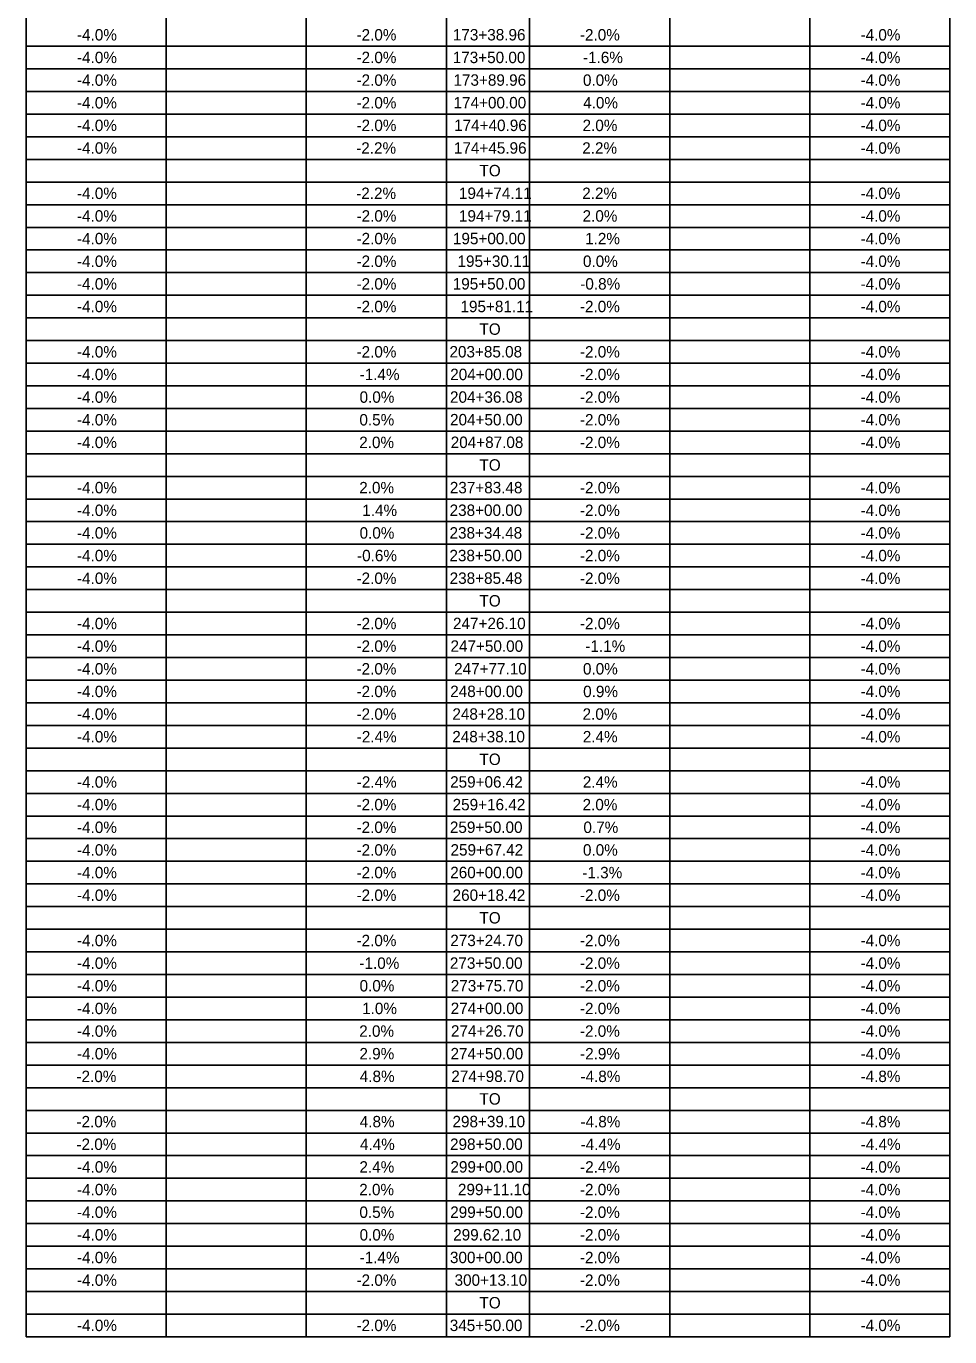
# Model space of a CAD drawing. Extents: x -15319374 to 1762012, y 465773 to 3693661.
# Drawn here: x -15318877.5 to -15318635, y 3691285.9 to 3691629.9 of the extents above; entities that cross this region are included whole.
import ezdxf

# ---------------------------------------------------------------- set-up
doc = ezdxf.new("R2010")
doc.units = 0
doc.layers.add('BORDER', color=7, linetype='Continuous')
doc.layers.add('DIMENSIONS', color=7, linetype='Continuous')

msp = doc.modelspace()

# ---------------------------------------------------------------- linework, layer by layer
at = {"layer": 'BORDER'}
for p, q in [((-15318877.49, 3691969.22), (-15318877.49, 3691464.16)), ((-15318840.73, 3691969.22), (-15318840.73, 3691285.88)), ((-15318803.96, 3691969.22), (-15318803.96, 3691285.88)), ((-15318767.19, 3691969.22), (-15318767.19, 3691285.88)), ((-15318745.32, 3691969.22), (-15318745.32, 3691285.88)), ((-15318708.55, 3691969.22), (-15318708.55, 3691285.88)), ((-15318671.78, 3691969.22), (-15318671.78, 3691285.88)), ((-15318635.01, 3691969.22), (-15318635.01, 3691464.16)), ((-15318877.49, 3691963.35), (-15318877.49, 3691285.88)), ((-15318877.49, 3691624.61), (-15318635.01, 3691624.61)), ((-15318877.49, 3691618.67), (-15318635.01, 3691618.67)), ((-15318877.49, 3691612.73), (-15318635.01, 3691612.73)), ((-15318877.49, 3691606.78), (-15318635.01, 3691606.78)), ((-15318877.49, 3691600.84), (-15318635.01, 3691600.84)), ((-15318877.49, 3691594.9), (-15318635.01, 3691594.9)), ((-15318877.49, 3691588.96), (-15318635.01, 3691588.96)), ((-15318877.49, 3691583.01), (-15318635.01, 3691583.01)), ((-15318877.49, 3691577.07), (-15318635.01, 3691577.07)), ((-15318877.49, 3691571.13), (-15318635.01, 3691571.13)), ((-15318877.49, 3691565.19), (-15318635.01, 3691565.19)), ((-15318877.49, 3691559.24), (-15318635.01, 3691559.24)), ((-15318877.49, 3691553.3), (-15318635.01, 3691553.3)), ((-15318877.49, 3691547.36), (-15318635.01, 3691547.36)), ((-15318877.49, 3691541.41), (-15318635.01, 3691541.41)), ((-15318877.49, 3691535.47), (-15318635.01, 3691535.47)), ((-15318877.49, 3691529.53), (-15318635.01, 3691529.53)), ((-15318877.49, 3691523.59), (-15318635.01, 3691523.59)), ((-15318877.49, 3691517.64), (-15318635.01, 3691517.64)), ((-15318877.49, 3691511.7), (-15318635.01, 3691511.7)), ((-15318877.49, 3691505.76), (-15318635.01, 3691505.76)), ((-15318877.49, 3691499.82), (-15318635.01, 3691499.82)), ((-15318877.49, 3691493.87), (-15318635.01, 3691493.87)), ((-15318877.49, 3691487.93), (-15318635.01, 3691487.93)), ((-15318877.49, 3691481.99), (-15318635.01, 3691481.99)), ((-15318877.49, 3691476.04), (-15318635.01, 3691476.04)), ((-15318877.49, 3691470.1), (-15318635.01, 3691470.1)), ((-15318877.49, 3691464.16), (-15318635.01, 3691464.16)), ((-15318877.49, 3691458.22), (-15318635.01, 3691458.22)), ((-15318877.49, 3691452.27), (-15318635.01, 3691452.27)), ((-15318877.49, 3691446.33), (-15318635.01, 3691446.33)), ((-15318877.49, 3691440.39), (-15318635.01, 3691440.39)), ((-15318877.49, 3691434.45), (-15318635.01, 3691434.45)), ((-15318877.49, 3691428.5), (-15318635.01, 3691428.5)), ((-15318877.49, 3691422.56), (-15318635.01, 3691422.56)), ((-15318877.49, 3691416.62), (-15318635.01, 3691416.62)), ((-15318877.49, 3691410.67), (-15318635.01, 3691410.67)), ((-15318877.49, 3691404.73), (-15318635.01, 3691404.73)), ((-15318877.49, 3691398.79), (-15318635.01, 3691398.79)), ((-15318877.49, 3691392.85), (-15318635.01, 3691392.85)), ((-15318877.49, 3691386.9), (-15318635.01, 3691386.9)), ((-15318877.49, 3691380.96), (-15318635.01, 3691380.96)), ((-15318877.49, 3691375.02), (-15318635.01, 3691375.02)), ((-15318877.49, 3691369.08), (-15318635.01, 3691369.08)), ((-15318877.49, 3691363.13), (-15318635.01, 3691363.13)), ((-15318877.49, 3691357.19), (-15318635.01, 3691357.19)), ((-15318877.49, 3691351.25), (-15318635.01, 3691351.25)), ((-15318877.49, 3691345.31), (-15318635.01, 3691345.31)), ((-15318877.49, 3691339.36), (-15318635.01, 3691339.36)), ((-15318877.49, 3691333.42), (-15318635.01, 3691333.42)), ((-15318877.49, 3691327.48), (-15318635.01, 3691327.48)), ((-15318877.49, 3691321.53), (-15318635.01, 3691321.53)), ((-15318877.49, 3691315.59), (-15318635.01, 3691315.59)), ((-15318877.49, 3691309.65), (-15318635.01, 3691309.65)), ((-15318877.49, 3691303.71), (-15318635.01, 3691303.71)), ((-15318877.49, 3691297.76), (-15318635.01, 3691297.76)), ((-15318877.49, 3691291.82), (-15318635.01, 3691291.82)), ((-15318877.49, 3691285.88), (-15318635.01, 3691285.88))]:
    msp.add_line(p, q, dxfattribs=at)
for points in [[(-15318877.49, 3691969.22), (-15318635.01, 3691969.22), (-15318635.01, 3691624.61), (-15318877.49, 3691624.61)], [(-15318877.49, 3691624.61), (-15318635.01, 3691624.61), (-15318635.01, 3691285.88), (-15318877.49, 3691285.88)]]:
    msp.add_lwpolyline(points, close=True, dxfattribs=at)

# ---------------------------------------------------------------- texts
at = {"layer": 'DIMENSIONS'}
for s, p in [('-4.0%', (-15318864.16, 3691626.1)), ('-2.0%', (-15318790.77, 3691626.1)), ('173+38.96', (-15318765.48, 3691626.12)), ('-2.0%', (-15318732.12, 3691626.1)), ('-4.0%', (-15318658.45, 3691626.1)), ('-4.0%', (-15318864.16, 3691620.16)), ('-2.0%', (-15318790.77, 3691620.16)), ('173+50.00', (-15318765.51, 3691620.17)), ('-1.6%', (-15318731.32, 3691620.16)), ('-4.0%', (-15318658.45, 3691620.16)), ('-4.0%', (-15318864.16, 3691614.21)), ('-2.0%', (-15318790.77, 3691614.21)), ('173+89.96', (-15318765.32, 3691614.23)), ('0.0%', (-15318731.32, 3691614.21)), ('-4.0%', (-15318658.45, 3691614.21)), ('-4.0%', (-15318864.16, 3691608.27)), ('-2.0%', (-15318790.77, 3691608.27)), ('174+00.00', (-15318765.3, 3691608.29)), ('4.0%', (-15318731.27, 3691608.27)), ('-4.0%', (-15318658.45, 3691608.27)), ('-4.0%', (-15318864.16, 3691602.33)), ('-2.0%', (-15318790.77, 3691602.33)), ('174+40.96', (-15318765.15, 3691602.34)), ('2.0%', (-15318731.42, 3691602.33)), ('-4.0%', (-15318658.45, 3691602.33)), ('-4.0%', (-15318864.16, 3691596.39)), ('-2.2%', (-15318790.86, 3691596.39)), ('174+45.96', (-15318765.2, 3691596.4)), ('2.2%', (-15318731.51, 3691596.39)), ('-4.0%', (-15318658.45, 3691596.39)), ('TO', (-15318758.49, 3691590.46)), ('-4.0%', (-15318864.16, 3691584.5)), ('-2.2%', (-15318790.86, 3691584.5)), ('194+74.11', (-15318763.88, 3691584.52)), ('2.2%', (-15318731.51, 3691584.5)), ('-4.0%', (-15318658.45, 3691584.5)), ('-4.0%', (-15318864.16, 3691578.56)), ('-2.0%', (-15318790.77, 3691578.56)), ('194+79.11', (-15318763.88, 3691578.57)), ('2.0%', (-15318731.42, 3691578.56)), ('-4.0%', (-15318658.45, 3691578.56)), ('-4.0%', (-15318864.16, 3691572.62)), ('-2.0%', (-15318790.77, 3691572.62)), ('195+00.00', (-15318765.46, 3691572.63)), ('1.2%', (-15318730.76, 3691572.62)), ('-4.0%', (-15318658.45, 3691572.62)), ('-4.0%', (-15318864.16, 3691566.67)), ('-2.0%', (-15318790.77, 3691566.67)), ('195+30.11', (-15318764.26, 3691566.69)), ('0.0%', (-15318731.32, 3691566.67)), ('-4.0%', (-15318658.45, 3691566.67)), ('-4.0%', (-15318864.16, 3691560.73)), ('-2.0%', (-15318790.77, 3691560.73)), ('195+50.00', (-15318765.51, 3691560.75)), ('-0.8%', (-15318732.03, 3691560.73)), ('-4.0%', (-15318658.45, 3691560.73)), ('-4.0%', (-15318864.16, 3691554.79)), ('-2.0%', (-15318790.77, 3691554.79)), ('195+81.11', (-15318763.48, 3691554.8)), ('-2.0%', (-15318732.12, 3691554.79)), ('-4.0%', (-15318658.45, 3691554.79)), ('TO', (-15318758.49, 3691548.86)), ('-4.0%', (-15318864.16, 3691542.9)), ('-2.0%', (-15318790.77, 3691542.9)), ('203+85.08', (-15318766.37, 3691542.92)), ('-2.0%', (-15318732.12, 3691542.9)), ('-4.0%', (-15318658.45, 3691542.9)), ('-4.0%', (-15318864.16, 3691536.96)), ('-1.4%', (-15318789.96, 3691536.96)), ('204+00.00', (-15318766.17, 3691536.97)), ('-2.0%', (-15318732.12, 3691536.96)), ('-4.0%', (-15318658.45, 3691536.96)), ('-4.0%', (-15318864.16, 3691531.02)), ('0.0%', (-15318789.97, 3691531.02)), ('204+36.08', (-15318766.23, 3691531.03)), ('-2.0%', (-15318732.12, 3691531.02)), ('-4.0%', (-15318658.45, 3691531.02)), ('-4.0%', (-15318864.16, 3691525.07)), ('0.5%', (-15318790.01, 3691525.07)), ('204+50.00', (-15318766.22, 3691525.09)), ('-2.0%', (-15318732.12, 3691525.07)), ('-4.0%', (-15318658.45, 3691525.07)), ('-4.0%', (-15318864.16, 3691519.13)), ('2.0%', (-15318790.06, 3691519.13)), ('204+87.08', (-15318766.04, 3691519.15)), ('-2.0%', (-15318732.12, 3691519.13)), ('-4.0%', (-15318658.45, 3691519.13)), ('TO', (-15318758.49, 3691513.2)), ('-4.0%', (-15318864.16, 3691507.25)), ('2.0%', (-15318790.06, 3691507.25)), ('237+83.48', (-15318766.28, 3691507.26)), ('-2.0%', (-15318732.12, 3691507.25)), ('-4.0%', (-15318658.45, 3691507.25)), ('-4.0%', (-15318864.16, 3691501.3)), ('1.4%', (-15318789.26, 3691501.3)), ('238+00.00', (-15318766.33, 3691501.32)), ('-2.0%', (-15318732.12, 3691501.3)), ('-4.0%', (-15318658.45, 3691501.3)), ('-4.0%', (-15318864.16, 3691495.36)), ('0.0%', (-15318789.97, 3691495.36)), ('238+34.48', (-15318766.35, 3691495.38)), ('-2.0%', (-15318732.12, 3691495.36)), ('-4.0%', (-15318658.45, 3691495.36)), ('-4.0%', (-15318864.16, 3691489.42)), ('-0.6%', (-15318790.63, 3691489.42)), ('238+50.00', (-15318766.38, 3691489.43)), ('-2.0%', (-15318732.12, 3691489.42)), ('-4.0%', (-15318658.45, 3691489.42)), ('-4.0%', (-15318864.16, 3691483.47)), ('-2.0%', (-15318790.77, 3691483.47)), ('238+85.48', (-15318766.32, 3691483.49)), ('-2.0%', (-15318732.12, 3691483.47)), ('-4.0%', (-15318658.45, 3691483.47)), ('TO', (-15318758.49, 3691477.55)), ('-4.0%', (-15318864.16, 3691471.59)), ('-2.0%', (-15318790.77, 3691471.59)), ('247+26.10', (-15318765.44, 3691471.61)), ('-2.0%', (-15318732.12, 3691471.59)), ('-4.0%', (-15318658.45, 3691471.59)), ('-4.0%', (-15318864.16, 3691465.65)), ('-2.0%', (-15318790.77, 3691465.65)), ('247+50.00', (-15318766.1, 3691465.66)), ('-1.1%', (-15318730.71, 3691465.65)), ('-4.0%', (-15318658.45, 3691465.65)), ('-4.0%', (-15318864.16, 3691459.7)), ('-2.0%', (-15318790.77, 3691459.7)), ('247+77.10', (-15318765.15, 3691459.72)), ('0.0%', (-15318731.32, 3691459.7)), ('-4.0%', (-15318658.45, 3691459.7)), ('-4.0%', (-15318864.16, 3691453.76)), ('-2.0%', (-15318790.77, 3691453.76)), ('248+00.00', (-15318766.17, 3691453.78)), ('0.9%', (-15318731.27, 3691453.76)), ('-4.0%', (-15318658.45, 3691453.76)), ('-4.0%', (-15318864.16, 3691447.82)), ('-2.0%', (-15318790.77, 3691447.82)), ('248+28.10', (-15318765.6, 3691447.83)), ('2.0%', (-15318731.42, 3691447.82)), ('-4.0%', (-15318658.45, 3691447.82)), ('-4.0%', (-15318864.16, 3691441.88)), ('-2.4%', (-15318790.72, 3691441.88)), ('248+38.10', (-15318765.63, 3691441.89)), ('2.4%', (-15318731.37, 3691441.88)), ('-4.0%', (-15318658.45, 3691441.88)), ('TO', (-15318758.49, 3691435.95)), ('-4.0%', (-15318864.16, 3691429.99)), ('-2.4%', (-15318790.72, 3691429.99)), ('259+06.42', (-15318766.2, 3691430.01)), ('2.4%', (-15318731.37, 3691429.99)), ('-4.0%', (-15318658.45, 3691429.99)), ('-4.0%', (-15318864.16, 3691424.05)), ('-2.0%', (-15318790.77, 3691424.05)), ('259+16.42', (-15318765.54, 3691424.06)), ('2.0%', (-15318731.42, 3691424.05)), ('-4.0%', (-15318658.45, 3691424.05)), ('-4.0%', (-15318864.16, 3691418.1)), ('-2.0%', (-15318790.77, 3691418.1)), ('259+50.00', (-15318766.26, 3691418.12)), ('0.7%', (-15318731.2, 3691418.1)), ('-4.0%', (-15318658.45, 3691418.1)), ('-4.0%', (-15318864.16, 3691412.16)), ('-2.0%', (-15318790.77, 3691412.16)), ('259+67.42', (-15318766.09, 3691412.18)), ('0.0%', (-15318731.32, 3691412.16)), ('-4.0%', (-15318658.45, 3691412.16)), ('-4.0%', (-15318864.16, 3691406.22)), ('-2.0%', (-15318790.77, 3691406.22)), ('260+00.00', (-15318766.17, 3691406.24)), ('-1.3%', (-15318731.49, 3691406.22)), ('-4.0%', (-15318658.45, 3691406.22)), ('-4.0%', (-15318864.16, 3691400.28)), ('-2.0%', (-15318790.77, 3691400.28)), ('260+18.42', (-15318765.54, 3691400.29)), ('-2.0%', (-15318732.12, 3691400.28)), ('-4.0%', (-15318658.45, 3691400.28)), ('TO', (-15318758.49, 3691394.35)), ('-4.0%', (-15318864.16, 3691388.39)), ('-2.0%', (-15318790.77, 3691388.39)), ('273+24.70', (-15318766.15, 3691388.41)), ('-2.0%', (-15318732.12, 3691388.39)), ('-4.0%', (-15318658.45, 3691388.39)), ('-4.0%', (-15318864.16, 3691382.45)), ('-1.0%', (-15318790.01, 3691382.45)), ('273+50.00', (-15318766.26, 3691382.46)), ('-2.0%', (-15318732.12, 3691382.45)), ('-4.0%', (-15318658.45, 3691382.45)), ('-4.0%', (-15318864.16, 3691376.51)), ('0.0%', (-15318789.97, 3691376.51)), ('273+75.70', (-15318766.03, 3691376.52)), ('-2.0%', (-15318732.12, 3691376.51)), ('-4.0%', (-15318658.45, 3691376.51)), ('-4.0%', (-15318864.16, 3691370.56)), ('1.0%', (-15318789.3, 3691370.56)), ('274+00.00', (-15318766.05, 3691370.58)), ('-2.0%', (-15318732.12, 3691370.56)), ('-4.0%', (-15318658.45, 3691370.56)), ('-4.0%', (-15318864.16, 3691364.62)), ('2.0%', (-15318790.06, 3691364.62)), ('274+26.70', (-15318765.98, 3691364.64)), ('-2.0%', (-15318732.12, 3691364.62)), ('-4.0%', (-15318658.45, 3691364.62)), ('-4.0%', (-15318864.16, 3691358.68)), ('2.9%', (-15318790.01, 3691358.68)), ('274+50.00', (-15318766.1, 3691358.69)), ('-2.9%', (-15318732.08, 3691358.68)), ('-4.0%', (-15318658.45, 3691358.68)), ('-2.0%', (-15318864.3, 3691352.73)), ('4.8%', (-15318789.92, 3691352.73)), ('274+98.70', (-15318765.89, 3691352.75)), ('-4.8%', (-15318731.98, 3691352.73)), ('-4.8%', (-15318658.45, 3691352.73)), ('TO', (-15318758.49, 3691346.81)), ('-2.0%', (-15318864.3, 3691340.85)), ('4.8%', (-15318789.92, 3691340.85)), ('298+39.10', (-15318765.58, 3691340.87)), ('-4.8%', (-15318731.98, 3691340.85)), ('-4.8%', (-15318658.45, 3691340.85)), ('-2.0%', (-15318864.3, 3691334.91)), ('4.4%', (-15318789.87, 3691334.91)), ('298+50.00', (-15318766.22, 3691334.92)), ('-4.4%', (-15318731.94, 3691334.91)), ('-4.4%', (-15318658.4, 3691334.91)), ('-4.0%', (-15318864.16, 3691328.96)), ('2.4%', (-15318790.01, 3691328.96)), ('299+00.00', (-15318766.12, 3691328.98)), ('-2.4%', (-15318732.08, 3691328.96)), ('-4.0%', (-15318658.45, 3691328.96)), ('-4.0%', (-15318864.16, 3691323.02)), ('2.0%', (-15318790.06, 3691323.02)), ('299+11.10', (-15318764.14, 3691323.04)), ('-2.0%', (-15318732.12, 3691323.02)), ('-4.0%', (-15318658.45, 3691323.02)), ('-4.0%', (-15318864.16, 3691317.08)), ('0.5%', (-15318790.01, 3691317.08)), ('299+50.00', (-15318766.17, 3691317.09)), ('-2.0%', (-15318732.12, 3691317.08)), ('-4.0%', (-15318658.45, 3691317.08)), ('-4.0%', (-15318864.16, 3691311.14)), ('0.0%', (-15318789.97, 3691311.14)), ('299.62.10', (-15318765.39, 3691311.15)), ('-2.0%', (-15318732.12, 3691311.14)), ('-4.0%', (-15318658.45, 3691311.14)), ('-4.0%', (-15318864.16, 3691305.19)), ('-1.4%', (-15318789.96, 3691305.19)), ('300+00.00', (-15318766.24, 3691305.21)), ('-2.0%', (-15318732.12, 3691305.19)), ('-4.0%', (-15318658.45, 3691305.19)), ('-4.0%', (-15318864.16, 3691299.25)), ('-2.0%', (-15318790.77, 3691299.25)), ('300+13.10', (-15318765.03, 3691299.27)), ('-2.0%', (-15318732.12, 3691299.25)), ('-4.0%', (-15318658.45, 3691299.25)), ('TO', (-15318758.49, 3691293.32)), ('-4.0%', (-15318864.16, 3691287.37)), ('-2.0%', (-15318790.77, 3691287.37)), ('345+50.00', (-15318766.29, 3691287.38)), ('-2.0%', (-15318732.12, 3691287.37)), ('-4.0%', (-15318658.45, 3691287.37))]:
    msp.add_text(s, height=3, dxfattribs=at).set_placement(p)

doc.saveas('drawing.dxf')
